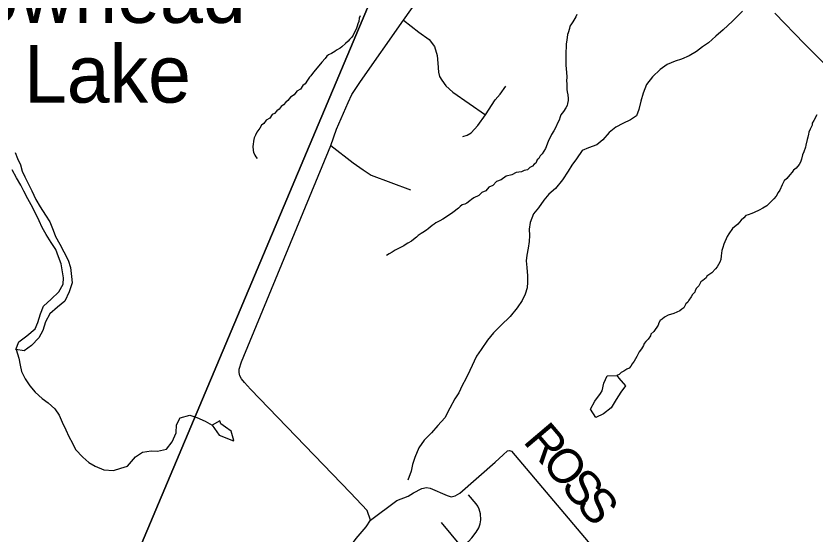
# Model space of a CAD drawing. Extents: x 0 to 34, y 0 to 22.
# Drawn here: x 2.928 to 4.243, y 18.554 to 19.406 of the extents above; entities that cross this region are included whole.
import ezdxf

# ---------------------------------------------------------------- set-up
doc = ezdxf.new("R2010")
doc.units = 0
for name, color, linetype in [('GM_X_Corporation', 7, 'Continuous'), ('GM_X_County_Road', 7, 'Continuous'), ('GM_X_Minor_Lake', 7, 'Continuous'), ('GM_X_Minor_Lake_Text', 7, 'Continuous'), ('GM_X_Minor_River', 7, 'Continuous'), ('GM_X_Rail_Line', 7, 'Continuous'), ('GM_X_Township_Road', 7, 'Continuous'), ('GM_X_Township_Road_Text', 7, 'Continuous')]:
    doc.layers.add(name, color=color, linetype=linetype)

msp = doc.modelspace()

# ---------------------------------------------------------------- linework, layer by layer
at = {"layer": 'GM_X_Corporation'}
for points in [[(2.9719, 18.1533), (3.7872, 20.088), (3.8522, 20.2422), (3.8409, 20.2497), (3.8323, 20.2612), (3.8208, 20.2827), (3.7655, 20.3086), (3.7425, 20.323), (3.7051, 20.3337), (3.6591, 20.356), (3.6132, 20.374), (3.5715, 20.4013), (3.5032, 20.4534), (3.4422, 20.5121), (3.3451, 20.6115), (3.3247, 20.6703), (3.3225, 20.7019), (3.3518, 20.8013)], [(3.7872, 20.088), (2.9719, 18.1533)]]:
    msp.add_lwpolyline(points, dxfattribs=at)
at = {"layer": 'GM_X_County_Road'}
for points in [[(3.5105, 18.5772), (3.505, 18.5927), (3.4777, 18.6221), (3.3136, 18.7923), (3.3038, 18.8032), (3.2988, 18.8097), (3.2956, 18.8143), (3.2946, 18.82), (3.2948, 18.8253), (3.2984, 18.8373), (3.4452, 19.1929), (3.455, 19.2198), (3.4738, 19.264), (3.4797, 19.2767), (3.4939, 19.2983), (3.5649, 19.3993), (3.5919, 19.4377)], [(3.2805, 18.2449), (3.2809, 18.2475), (3.2822, 18.2524), (3.2838, 18.2586), (3.2859, 18.2652), (3.2875, 18.27), (3.2897, 18.275), (3.2913, 18.2791), (3.2945, 18.2845), (3.2966, 18.2888), (3.2991, 18.2932), (3.3047, 18.3011), (3.352, 18.3643), (3.3648, 18.3829), (3.3698, 18.3895), (3.388, 18.4133), (3.4253, 18.4636), (3.4871, 18.5467), (3.5036, 18.5662), (3.5105, 18.5772)]]:
    msp.add_lwpolyline(points, dxfattribs=at)
at = {"layer": 'GM_X_Minor_Lake'}
for points in [[(3.9156, 18.8148), (3.9186, 18.8105), (3.9298, 18.7977), (3.922, 18.7876), (3.9142, 18.7752), (3.906, 18.762), (3.8936, 18.752), (3.8809, 18.7457), (3.8724, 18.7596), (3.8791, 18.7728), (3.8885, 18.7855)], [(3.8885, 18.7855), (3.8912, 18.7897), (3.8941, 18.8022), (3.8996, 18.8142), (3.9156, 18.8148)], [(3.2648, 18.7352), (3.263, 18.7402), (3.2503, 18.7332)], [(3.2503, 18.7332), (3.2618, 18.7166), (3.2856, 18.7075), (3.286, 18.7082), (3.2814, 18.7232), (3.2725, 18.7299), (3.2648, 18.7352)]]:
    msp.add_lwpolyline(points, dxfattribs=at)
at = {"layer": 'GM_X_Minor_River'}
for points in [[(3.4937, 19.4061), (3.4921, 19.4023), (3.4912, 19.397), (3.49, 19.3932), (3.4888, 19.3894), (3.4872, 19.3845), (3.4849, 19.3807), (3.4821, 19.3747), (3.4798, 19.3713), (3.4759, 19.3672), (3.474, 19.3646), (3.4697, 19.3608), (3.4636, 19.3552), (3.4605, 19.353), (3.4547, 19.3497), (3.452, 19.3475), (3.4463, 19.3445), (3.4417, 19.3419), (3.4386, 19.3397), (3.4362, 19.3363), (3.4304, 19.3303), (3.4231, 19.321), (3.4169, 19.3138), (3.4126, 19.3078), (3.4106, 19.3052), (3.4071, 19.3003), (3.4032, 19.2943), (3.3994, 19.2917), (3.3955, 19.2857), (3.3897, 19.2824), (3.385, 19.2764), (3.3789, 19.2723), (3.375, 19.267), (3.3712, 19.2644)], [(4.122, 19.414), (4.1057, 19.3972), (4.0899, 19.3834), (4.0779, 19.373), (4.0659, 19.3618), (4.0563, 19.3555), (4.0463, 19.3477), (4.0344, 19.3406), (4.0217, 19.3352), (4.0114, 19.3315), (3.998, 19.3261), (3.9868, 19.3179), (3.974, 19.306), (3.9643, 19.2932), (3.9587, 19.2792), (3.9547, 19.266), (3.9518, 19.2524), (3.9478, 19.2418), (3.9378, 19.2355), (3.9251, 19.2293), (3.9136, 19.2234), (3.9028, 19.2145), (3.8923, 19.2021), (3.8823, 19.1939), (3.8689, 19.1892), (3.8586, 19.1848), (3.8492, 19.1709), (3.8414, 19.1608), (3.8355, 19.151), (3.8261, 19.1367), (3.8145, 19.1225), (3.8037, 19.1132), (3.7955, 19.1034), (3.7865, 19.0907), (3.7784, 19.0805), (3.7732, 19.0662), (3.7715, 19.0556), (3.772, 19.0449), (3.7711, 19.0354), (3.7698, 19.0241), (3.7673, 19.0127), (3.7664, 19.0032), (3.7673, 18.9922), (3.7686, 18.9785), (3.7688, 18.9686), (3.7683, 18.9591), (3.765, 18.9485), (3.7599, 18.9383), (3.7517, 18.9263), (3.7404, 18.912), (3.7249, 18.8971), (3.7126, 18.8852), (3.7028, 18.8732), (3.6923, 18.8578), (3.6849, 18.8469), (3.6738, 18.8231), (3.6671, 18.8092), (3.6612, 18.7986), (3.6557, 18.7862), (3.6494, 18.7764), (3.6412, 18.7613), (3.6329, 18.7455), (3.6213, 18.7328), (3.6108, 18.7208), (3.5988, 18.7085), (3.5902, 18.6961), (3.5834, 18.6799), (3.5798, 18.6685), (3.5777, 18.6579), (3.5721, 18.6428)], [(3.8496, 19.4082), (3.848, 19.4048), (3.8449, 19.3992), (3.8433, 19.3961), (3.8398, 19.3916), (3.8382, 19.389), (3.8374, 19.3852), (3.8354, 19.3784), (3.8342, 19.3758), (3.8337, 19.3708), (3.8328, 19.3632), (3.8324, 19.3602), (3.8323, 19.353), (3.8318, 19.3488), (3.8316, 19.3351), (3.8318, 19.3244), (3.8321, 19.3195), (3.833, 19.3058), (3.8329, 19.2989), (3.8332, 19.2951), (3.8331, 19.2879), (3.8334, 19.2852), (3.8337, 19.2814), (3.8348, 19.2765), (3.8355, 19.2704), (3.8354, 19.2673), (3.8346, 19.262), (3.8337, 19.259), (3.8314, 19.2549), (3.8279, 19.2492), (3.8236, 19.2436), (3.8224, 19.2402), (3.8204, 19.2349), (3.8184, 19.2311), (3.8145, 19.2221), (3.8117, 19.2172), (3.8078, 19.2111), (3.8055, 19.2051), (3.8031, 19.201), (3.7995, 19.1911), (3.798, 19.1881), (3.7929, 19.1791), (3.7894, 19.1761), (3.7874, 19.1716), (3.7847, 19.1693), (3.7823, 19.164), (3.7793, 19.1622), (3.7769, 19.1588)], [(3.3712, 19.2644), (3.3677, 19.2599), (3.3638, 19.2573), (3.3607, 19.2528), (3.3565, 19.2502), (3.353, 19.2457), (3.3488, 19.2439), (3.3449, 19.2379), (3.3391, 19.2349), (3.3352, 19.2293), (3.3314, 19.2267), (3.3286, 19.2218), (3.3255, 19.2173), (3.3236, 19.2147), (3.3216, 19.2101), (3.3196, 19.2056), (3.3184, 19.1999), (3.3179, 19.1946), (3.3175, 19.192), (3.3177, 19.1851), (3.3181, 19.1821), (3.3203, 19.1771), (3.3221, 19.1744), (3.3243, 19.1717)], [(4.2441, 19.2434), (4.239, 19.234), (4.2362, 19.2299), (4.2362, 19.2265), (4.2334, 19.2197), (4.231, 19.2148), (4.2306, 19.2117), (4.2294, 19.2068), (4.2282, 19.203), (4.2261, 19.1935), (4.2253, 19.1901), (4.2229, 19.1826), (4.2205, 19.1777), (4.2189, 19.1708), (4.2173, 19.1659), (4.2149, 19.1618), (4.2103, 19.1558), (4.2057, 19.1524), (4.2037, 19.1491), (4.1995, 19.1449), (4.1948, 19.1389), (4.1902, 19.1348), (4.1874, 19.1284), (4.1834, 19.1197), (4.1807, 19.116), (4.1772, 19.1096), (4.1737, 19.1051), (4.1694, 19.1017), (4.166, 19.0976), (4.1617, 19.0939), (4.1556, 19.0898), (4.1494, 19.0865), (4.141, 19.0828), (4.1375, 19.0814), (4.131, 19.0788), (4.1276, 19.0777), (4.1241, 19.0744), (4.1195, 19.0703), (4.1141, 19.0635), (4.1056, 19.0564), (4.0997, 19.0478), (4.097, 19.0433), (4.0911, 19.0308), (4.0895, 19.0252), (4.0882, 19.0206), (4.0869, 19.0115), (4.0861, 19.0058), (4.0845, 19.0013), (4.0802, 18.9934), (4.0775, 18.9904), (4.0713, 18.9836), (4.0636, 18.9784), (4.0624, 18.9754), (4.057, 18.9709), (4.0535, 18.9687), (4.05, 18.9623), (4.0465, 18.9586), (4.0442, 18.9548), (4.0437, 18.9518), (4.0395, 18.9481), (4.0375, 18.9443), (4.034, 18.939), (4.0321, 18.9356), (4.029, 18.9326), (4.0254, 18.9262), (4.0224, 18.924), (4.0189, 18.9214), (4.0093, 18.917), (3.9998, 18.9141), (3.994, 18.9108), (3.9898, 18.9075), (3.9867, 18.9052), (3.9843, 18.9015), (3.9835, 18.8977), (3.9761, 18.8875)], [(2.9264, 19.1817), (2.9304, 19.1718), (2.9356, 19.1614), (2.9384, 19.1511), (2.9428, 19.1415), (2.948, 19.1308), (2.9542, 19.1185), (2.9608, 19.1043), (2.9678, 19.0921), (2.9767, 19.0786), (2.9834, 19.0675), (2.9892, 19.0537), (2.9932, 19.0437), (2.9999, 19.031), (3.0069, 19.0184), (3.0135, 19.0046), (3.0175, 18.9923), (3.0195, 18.9775), (3.0201, 18.9672), (3.0152, 18.9525), (3.0085, 18.937), (2.9965, 18.9273), (2.9834, 18.9162), (2.9767, 18.903), (2.9719, 18.889), (2.9656, 18.8769), (2.9536, 18.8642), (2.9413, 18.8557), (2.928, 18.8578), (2.9328, 18.8703), (2.9459, 18.8803)], [(3.7769, 19.1588), (3.7727, 19.157), (3.7685, 19.1529), (3.7631, 19.1518), (3.7585, 19.15), (3.7501, 19.1486), (3.7429, 19.145), (3.7333, 19.1425), (3.7256, 19.1365), (3.7176, 19.1336), (3.7118, 19.1272), (3.7053, 19.1247), (3.7002, 19.1187), (3.6937, 19.1158), (3.6887, 19.1109), (3.6806, 19.1069), (3.6768, 19.1043), (3.6737, 19.102), (3.6691, 19.0983), (3.6656, 19.0965), (3.6614, 19.0954), (3.658, 19.0928), (3.6552, 19.0898), (3.646, 19.0831), (3.6406, 19.079), (3.6295, 19.072), (3.6245, 19.069), (3.618, 19.0657), (3.6153, 19.0635), (3.6118, 19.0617), (3.6056, 19.0561), (3.6029, 19.0538), (3.5964, 19.0501), (3.5937, 19.0483), (3.5891, 19.0449), (3.5864, 19.0423), (3.581, 19.0386), (3.5779, 19.036), (3.5718, 19.0323), (3.5691, 19.0308), (3.5652, 19.0282), (3.5587, 19.0246), (3.5514, 19.0209), (3.5464, 19.0179), (3.5411, 19.015), (3.5368, 19.0124)], [(2.9459, 18.8803), (2.9594, 18.8919), (2.9641, 18.902), (2.9682, 18.9164), (2.9734, 18.9289), (2.9857, 18.9404), (2.9985, 18.9524), (3.0056, 18.9652), (3.0061, 18.9754), (3.0041, 18.9888), (3.002, 18.9987), (2.998, 19.0102), (2.9936, 19.022), (2.9858, 19.0336), (2.9777, 19.047), (2.9711, 19.0582), (2.9659, 19.0693), (2.9597, 19.0831), (2.9531, 19.0954), (2.9475, 19.1053), (2.9409, 19.118), (2.9357, 19.1276), (2.9291, 19.1399), (2.9217, 19.1529)], [(3.9761, 18.8875), (3.9711, 18.8831), (3.9707, 18.88), (3.9668, 18.8748), (3.9633, 18.8707), (3.9606, 18.8673), (3.9594, 18.8643), (3.9559, 18.859), (3.952, 18.8537), (3.95, 18.8496), (3.9481, 18.8462), (3.9441, 18.8387), (3.9406, 18.8342), (3.9383, 18.8304), (3.9356, 18.827), (3.9321, 18.8252), (3.9267, 18.8218), (3.9225, 18.8196), (3.919, 18.8163), (3.9156, 18.8148)], [(2.9281, 18.8578), (2.9326, 18.8435), (2.9348, 18.8318), (2.9369, 18.8215), (2.9431, 18.8097), (2.9505, 18.7977), (2.9595, 18.7873), (2.9711, 18.7772), (2.9809, 18.7702), (2.9917, 18.7601), (2.9988, 18.7498), (3.0039, 18.7383), (3.0101, 18.7256), (3.0149, 18.7145), (3.0208, 18.7034), (3.0259, 18.6934), (3.0379, 18.6807), (3.0476, 18.6721), (3.0582, 18.6659), (3.0721, 18.6599), (3.0885, 18.6589), (3.1004, 18.6628), (3.1111, 18.6657), (3.1246, 18.681), (3.1358, 18.6888), (3.1503, 18.6908), (3.1606, 18.6903), (3.1751, 18.6938), (3.1848, 18.7058), (3.1915, 18.7205), (3.1918, 18.7338), (3.198, 18.7455), (3.2137, 18.7498), (3.2254, 18.7458), (3.2387, 18.7399), (3.2503, 18.7332)]]:
    msp.add_lwpolyline(points, dxfattribs=at)
at = {"layer": 'GM_X_Rail_Line'}
msp.add_lwpolyline([(4.1749, 19.4105), (4.2237, 19.36), (4.2875, 19.2967)], dxfattribs=at)
at = {"layer": 'GM_X_Township_Road'}
msp.add_line((3.6591, 18.5349), (3.6272, 18.573), dxfattribs=at)
for points in [[(3.5649, 19.3993), (3.5903, 19.3794), (3.6069, 19.3675), (3.6157, 19.3557), (3.6203, 19.3411), (3.6211, 19.3284), (3.6226, 19.3136), (3.6242, 19.3065), (3.6278, 19.3002), (3.6344, 19.2913), (3.6461, 19.281), (3.6997, 19.2437)], [(3.6624, 19.2079), (3.6697, 19.21), (3.6763, 19.2139), (3.687, 19.2258), (3.6997, 19.2437), (3.7155, 19.2679), (3.7238, 19.2777), (3.7332, 19.2906)], [(3.4452, 19.1929), (3.4821, 19.1648), (3.4986, 19.1531), (3.5119, 19.1441), (3.5763, 19.1204)], [(3.5105, 18.5772), (3.5539, 18.6094), (3.5723, 18.6167), (3.581, 18.6221), (3.5947, 18.6294), (3.6026, 18.6309), (3.6085, 18.6295), (3.6367, 18.6179), (3.6433, 18.6154), (3.6499, 18.6171), (3.6574, 18.6212), (3.7156, 18.6723), (3.7286, 18.6844), (3.736, 18.6909), (3.7389, 18.6915), (3.7422, 18.6906), (3.8743, 18.5343)], [(3.6591, 18.5349), (3.6659, 18.5383), (3.6714, 18.5421), (3.6773, 18.5479), (3.6844, 18.5575), (3.6887, 18.5647), (3.6909, 18.571), (3.692, 18.5776), (3.6915, 18.5875), (3.6891, 18.5954), (3.6868, 18.5999), (3.684, 18.604), (3.6716, 18.6185)]]:
    msp.add_lwpolyline(points, dxfattribs=at)

# ---------------------------------------------------------------- texts
at = {"layer": 'GM_X_Minor_Lake_Text'}
for s, rotation, p in [('Arrowhead', 0.0004, (2.6931, 19.3946)), ('Lake', 0.0005, (2.941, 19.2635))]:
    msp.add_text(s, height=0.0947, rotation=rotation, dxfattribs=at).set_placement(p)
at = {"layer": 'GM_X_Township_Road_Text'}
for s, rotation, p in [('R', 310.3528, (3.76, 18.7061)), ('O', 309.8154, (3.7901, 18.6706)), ('S', 309.8056, (3.8221, 18.6322)), ('S', 309.8056, (3.8466, 18.6028))]:
    msp.add_text(s, height=0.0568, rotation=rotation, dxfattribs=at).set_placement(p)

doc.saveas('drawing.dxf')
